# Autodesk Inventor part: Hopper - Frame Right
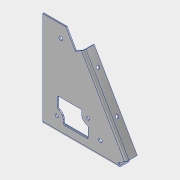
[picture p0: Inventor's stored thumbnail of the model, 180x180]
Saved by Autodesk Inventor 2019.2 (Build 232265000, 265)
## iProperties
Created: 2005-11
Part Number: Hopper - Frame Right
Document SubType Name: Sheet Metal
Designer: floress
Material: Aluminum 6061
Density: 2.7 g/cm^3
Sheet Metal Rule: Default
Appearance: Aluminum - Flat
Flat Pattern Width: 12.2582 cm
Flat Pattern Length: 14.0116 cm
Flat Pattern Area: 171.757 cm^2
Sheet Metal Width: 4.826 in
Sheet Metal Length: 5.516 in
Sheet Metal Area: 26.622 in^2
Author: floress
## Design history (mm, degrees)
node "Face1"
node "Flange1"
node "Flange2"
sketch "Sketch4"
  geometry: L1 (0, 0)-(0, 11.112) reference; L2 (101.6, 11.113)-(101.6, 0) reference; C1 r 1.778 at (12.7, 5.556); C2 r 1.778 at (88.9, 5.556); 1 further point
  constraints: 2 centre point, 2 horizontal alignment, 1 equal radius, 1 midpoint
  dimensions: "d21" = 3.556 diameter of C1; "d22" = 12.7 distance from line of L1 C1.centre; "d23" = 12.7 distance from line of L2 C2.centre
cut "Cut1" sketch "Sketch4" dims "d24" = 1.5875 (= Thickness), "d25" = 0
cut "Cut2" dims "d27" = 1.5875 (= Thickness), "d28" = 0
cut "Cut3" dims "d35" = 3.175 (= 2 x Thickness), "d36" = 0
sketch "Sketch7"
  geometry: L1 (-46.369, -108.828)-(6.781, -16.77); L2 (-20.949, -17.235)-(-78.784, -117.408) reference; C1 r 2.54 at (-46.369, -108.828); C2 r 2.54 at (6.781, -16.77); 1 further point
  constraints: 2 centre point, 2 coincident, 2 end point, 1 parallel
  dimensions: "d39" = 106.299 distance of L1.start L1.end; "d40" = 5.08 diameter of C1; "d41" = 5.08 diameter of C2
cut "Cut4" sketch "Sketch7" dims "d42" = 1.5875 (= Thickness), "d43" = 0
body "Solid1"
sketch "Sketch1"
  geometry: L1 (-65.393, 63.5)-(-34.328, 63.5); L2 (36.207, -63.5)-(-65.393, -63.5); L3 (-65.393, -63.5)-(-65.393, 63.5); L4 (-34.328, 63.5)-(-21.628, 41.503); L5 (-21.628, 41.503)-(-10.63, 47.853); L6 (-10.63, 47.853)-(47.205, -52.321); L7 (36.207, -63.5)-(36.207, -58.671); L8 (36.207, -58.671)-(47.205, -52.321); 3 further points
  constraints: 16 end point, 4 parallel, 3 perpendicular, 1 horizontal, 1 horizontal alignment, 1 midpoint, 1 vertical alignment
  dimensions: "d1" = 127 distance of L2.end L1.start; "d2" = 12.7 distance of L4.end L5.end; "d3" = 25.4 distance of L1.end L4.end; "d4" = 60 deg angle of L2 L6; "d20" = 101.6 distance of L2.start L2.end
face "Plate1" dims "d37" = 1.5875 (= Thickness)
sketch "Sketch2"
  geometry: L1 through (-50.8, 0) direction (-1, 0); L2 (-101.6, 0)-(-101.6, -12.7); L3 (-101.6, -12.7)-(0, -12.7); L4 through (0, -6.35) direction (0, 1)
  constraints: 6 end point, 1 horizontal, 1 perpendicular, 1 vertical
face "Plate2" dims "d6" = 1.5875 (= BendReliefWidth), "d8" = 3.175 (= MinimumRemnant), "d10" = 12.7, "d11" = 90 deg, "d12" = 1.5875 (= BendRadius), "d37" = 1.5875 (= Thickness)
bend "Bend1" dims "d6" = 1.5875 (= BendReliefWidth), "d7" = 0.79375 (= BendReliefDepth), "d8" = 3.175 (= MinimumRemnant), "d9" = 1.5875 (= BendRadius), "d10" = 12.7, "d11" = 90 deg, "d12" = 1.5875 (= BendRadius), "d37" = 1.5875 (= Thickness), "SeamGap" = 0.00508
sketch "Sketch3"
  geometry: L1 through (-57.835, 0) direction (-1, -4.26e-33); L2 (-115.67, 0)-(-115.67, -12.7); L3 (-115.67, -12.7)-(0, -12.7); L4 through (0, -6.35) direction (3.08e-33, 1)
  constraints: 6 end point, 1 horizontal, 1 perpendicular, 1 vertical
face "Plate3" dims "d13" = 1.5875 (= BendReliefWidth), "d15" = 3.175 (= MinimumRemnant), "d17" = 12.7, "d18" = 90 deg, "d19" = 1.5875 (= BendRadius), "d37" = 1.5875 (= Thickness)
bend "Bend2" dims "d13" = 1.5875 (= BendReliefWidth), "d14" = 0.79375 (= BendReliefDepth), "d15" = 3.175 (= MinimumRemnant), "d16" = 1.5875 (= BendRadius), "d17" = 12.7, "d18" = 90 deg, "d19" = 1.5875 (= BendRadius), "d37" = 1.5875 (= Thickness), "SeamGap" = 0.00508
sketch "Sketch5"
  geometry: L1 (0, 0)-(11.112, 0) reference; C1 r 2.159 at (5.556, -21.346); C2 r 2.159 at (5.556, -72.84); 1 further point
  constraints: 2 centre point, 2 vertical alignment, 1 equal radius, 1 midpoint
  dimensions: "d26" = 4.318 diameter of C1
sketch "Sketch6"
  geometry: L1 (-21.395, -91.558)-(-21.395, -87.095); L2 (-19.808, -85.508)-(9.363, -85.508); L3 (3.614, -109.411)-(3.614, -113.855); L4 (2.026, -115.443)-(-28.276, -115.443) reference; L5 (10.95, -87.095)-(10.95, -99.666); L6 (-29.864, -113.856)-(-29.864, -101.525) reference; L7 (-28.855, -100.047)-(-26.579, -99.155); L8 (9.942, -101.144)-(9.003, -101.511); C1 r 2.134 at (-29.555, -91.558); C2 r 2.134 at (12.097, -109.411); A1 r 1.587 centre (9.363, -87.095) between (10.95, -87.095) and (9.363, -85.508); A2 r 1.587 centre (-19.808, -87.095) between (-19.808, -85.508) and (-21.395, -87.095); A3 r 1.587 centre (-28.276, -113.856) between (-29.864, -113.856) and (-28.276, -115.443); A4 r 1.587 centre (2.026, -113.855) between (2.026, -115.443) and (3.614, -113.855); A5 r 1.587 centre (-28.276, -101.525) between (-28.855, -100.047) and (-29.864, -101.525); A6 r 1.587 centre (9.363, -99.666) between (9.942, -101.144) and (10.95, -99.666); A7 r 8.16 centre (-29.555, -91.558) between (-26.579, -99.155) and (-21.395, -91.558); A8 r 8.484 centre (12.097, -109.411) between (9.003, -101.511) and (3.614, -109.411); 2 further points
  constraints: 16 end point, 16 point on circle, 16 tangent, 10 centre point, 5 equal radius, 2 concentric, 2 parallel, 2 perpendicular, 2 point on line, 1 horizontal, 1 vertical, 1 other
  dimensions: "d29" = 4.2672 diameter of C1; "d34" = 1.5875 radius of A1; "d38" = 1.5875 radius of A5
feature "Definition1"
other parameters: "Thickness" = 1.5875, "BendRadius" = 1.5875 (= Thickness), "BendReliefWidth" = 1.5875 (= Thickness), "BendReliefDepth" = 0.79375 (= 0.5 x Thickness), "CornerReliefSize" = 6.35 (= 4 x Thickness), "MinimumRemnant" = 3.175 (= 2 x Thickness), "TransitionRadius" = 1.5875 (= BendRadius), "d5" = 1.5875 (= BendRadius), "JacobiRadiusSize" = 1.5875 (= Thickness), "GapSize" = 1.5875 (= Thickness), "BendRadius" = 1.5875, "BendReliefDepth" = 0.79375, "BendReliefWidth" = 1.5875, "CornerReliefSize" = 6.35, "GapSize" = 1.5875, "JacobiRadiusSize" = 1.5875, "MinimumRemnant" = 3.175, "Thickness" = 1.5875, "TransitionRadius" = 1.5875
